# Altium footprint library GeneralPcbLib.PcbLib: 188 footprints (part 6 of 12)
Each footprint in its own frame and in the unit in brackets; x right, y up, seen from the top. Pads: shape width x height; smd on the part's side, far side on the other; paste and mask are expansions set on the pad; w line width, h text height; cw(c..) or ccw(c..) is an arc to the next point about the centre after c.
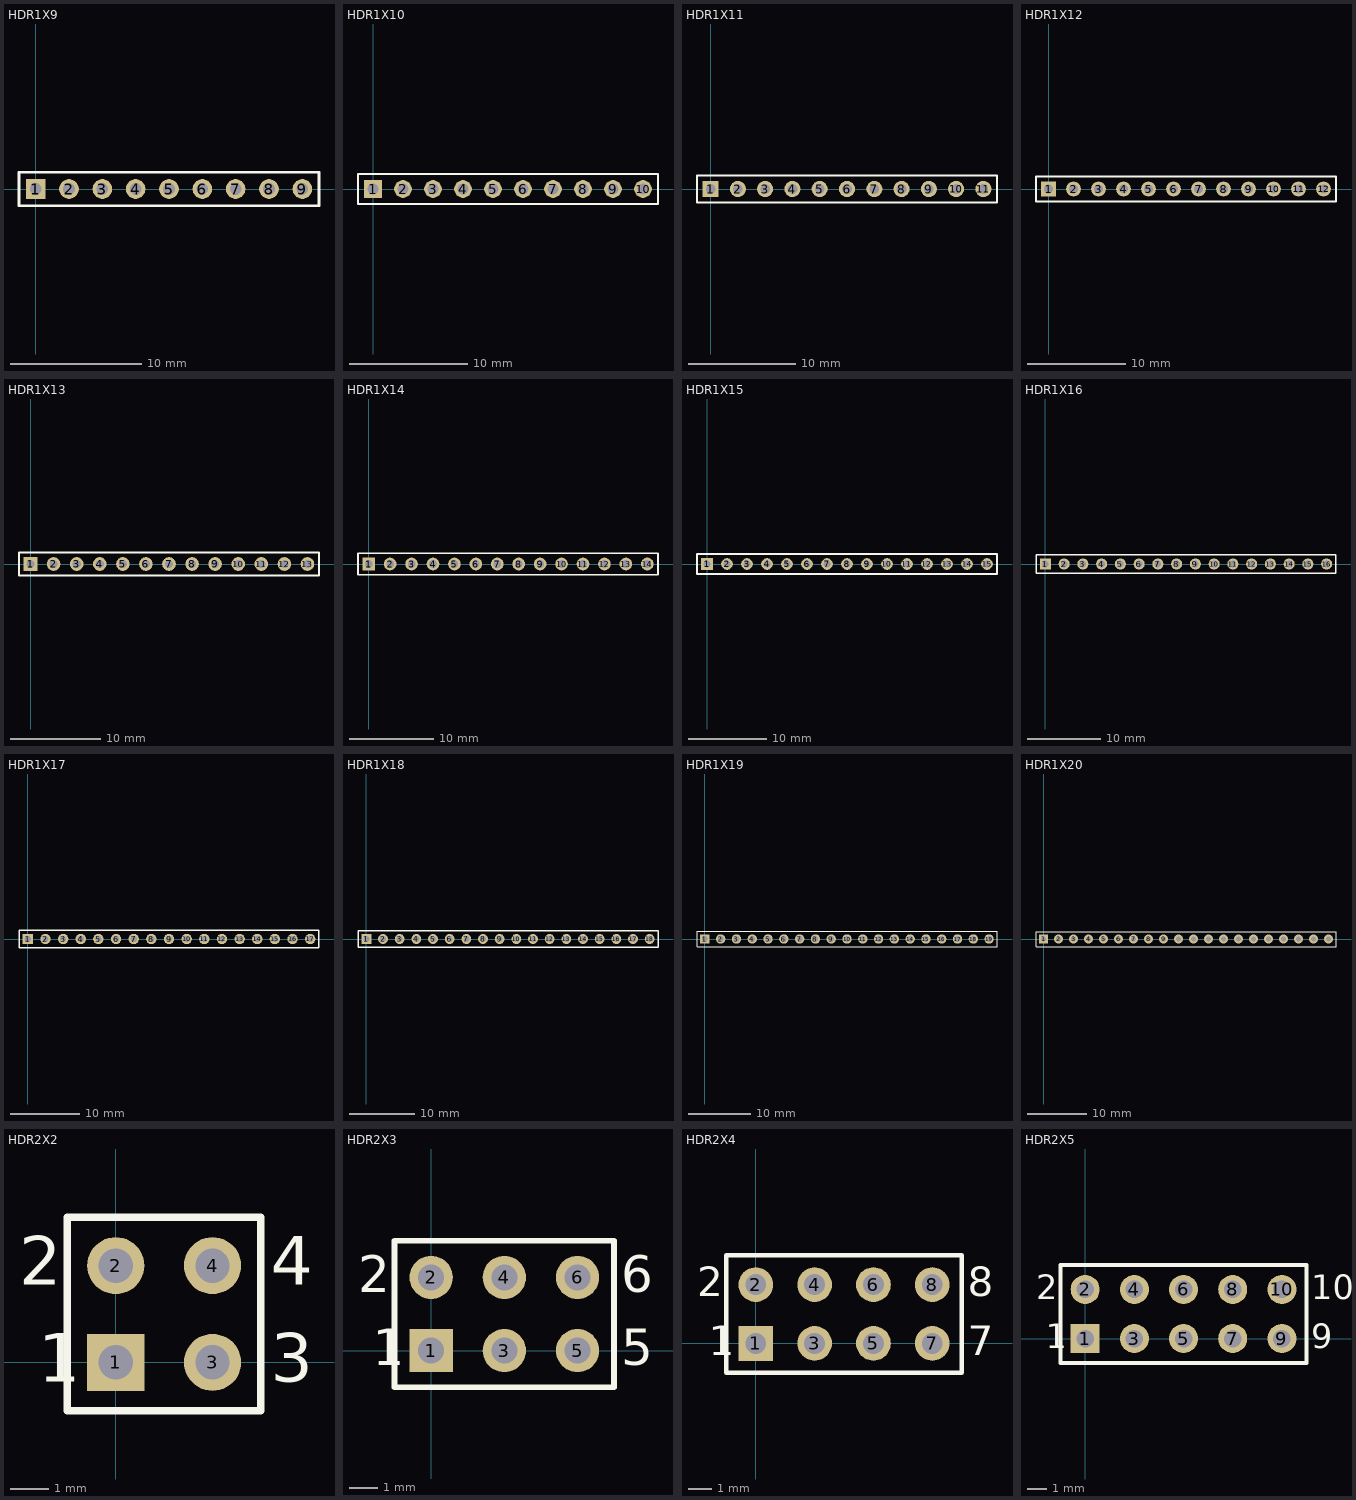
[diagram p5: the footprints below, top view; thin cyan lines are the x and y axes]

## HDR1X9 [mm] "Connector; Header; 9 Position"
pads (9):
  rect 1.5x1.5 hole 0.9: 1(0,0)
  round 1.5 hole 0.9: 2(2.54,0) 3(5.08,0) 4(7.62,0) 5(10.16,0) 6(12.7,0) 7(15.24,0) 8(17.78,0) 9(20.32,0)
Top Overlay:
  lines w0.2: -1.27,-1.27 21.59,-1.27 21.59,1.27 -1.27,1.27 -1.27,-1.27
3D body: height 7.58, standoff -2.94, extent 11.43,-1.27 13.97,1.27
3D body: height 7.58, standoff -2.94, extent 13.97,-1.27 16.51,1.27
3D body: height 7.58, standoff -2.94, extent 16.51,-1.27 19.05,1.27
3D body: height 7.58, standoff -2.94, extent 19.05,-1.27 21.59,1.27
3D body: height 7.58, standoff -2.94, extent 8.89,-1.27 11.43,1.27
3D body: height 7.58, standoff -2.94, extent 6.35,-1.27 8.89,1.27
3D body: height 7.58, standoff -2.94, extent 3.81,-1.27 6.35,1.27
3D body: height 7.58, standoff -2.94, extent 1.27,-1.27 3.81,1.27
3D body: height 7.58, standoff -2.94, extent -1.27,-1.27 1.27,1.27

## HDR1X10 [mm] "Connector; Header; 10 Position"
pads (10):
  rect 1.5x1.5 hole 0.9: 1(0,0)
  round 1.5 hole 0.9: 2(2.54,0) 3(5.08,0) 4(7.62,0) 5(10.16,0) 6(12.7,0) 7(15.24,0) 8(17.78,0) 9(20.32,0) 10(22.86,0)
Top Overlay:
  lines w0.2: -1.27,-1.27 24.13,-1.27 24.13,1.27 0.635,1.27 -1.27,1.27 -1.27,-1.27
3D body: height 7.58, standoff -2.94, extent 21.59,-1.27 24.13,1.27
3D body: height 7.58, standoff -2.94, extent 19.05,-1.27 21.59,1.27
3D body: height 7.58, standoff -2.94, extent 13.97,-1.27 16.51,1.27
3D body: height 7.58, standoff -2.94, extent 16.51,-1.27 19.05,1.27
3D body: height 7.58, standoff -2.94, extent 8.89,-1.27 11.43,1.27
3D body: height 7.58, standoff -2.94, extent 11.43,-1.27 13.97,1.27
3D body: height 7.58, standoff -2.94, extent 3.81,-1.27 6.35,1.27
3D body: height 7.58, standoff -2.94, extent 6.35,-1.27 8.89,1.27
3D body: height 7.58, standoff -2.94, extent 1.27,-1.27 3.81,1.27
3D body: height 7.58, standoff -2.94, extent -1.27,-1.27 1.27,1.27

## HDR1X11 [mm] "Connector; Header; 11 Position"
pads (11):
  rect 1.5x1.5 hole 0.9: 1(0,0)
  round 1.5 hole 0.9: 2(2.54,0) 3(5.08,0) 4(7.62,0) 5(10.16,0) 6(12.7,0) 7(15.24,0) 8(17.78,0) 9(20.32,0) 10(22.86,0) 11(25.4,0)
Top Overlay:
  lines w0.2: -1.27,-1.27 26.67,-1.27 26.67,1.27 0.635,1.27 -1.27,1.27 -1.27,-1.27
3D body: height 7.58, standoff -2.94, extent 24.13,-1.27 26.67,1.27
3D body: height 7.58, standoff -2.94, extent 21.59,-1.27 24.13,1.27
3D body: height 7.58, standoff -2.94, extent 19.05,-1.27 21.59,1.27
3D body: height 7.58, standoff -2.94, extent 16.51,-1.27 19.05,1.27
3D body: height 7.58, standoff -2.94, extent 13.97,-1.27 16.51,1.27
3D body: height 7.58, standoff -2.94, extent 11.43,-1.27 13.97,1.27
3D body: height 7.58, standoff -2.94, extent 8.89,-1.27 11.43,1.27
3D body: height 7.58, standoff -2.94, extent 6.35,-1.27 8.89,1.27
3D body: height 7.58, standoff -2.94, extent 3.81,-1.27 6.35,1.27
3D body: height 7.58, standoff -2.94, extent 1.27,-1.27 3.81,1.27
3D body: height 7.58, standoff -2.94, extent -1.27,-1.27 1.27,1.27

## HDR1X12 [mm] "Connector; Header; 12 Position"
pads (12):
  rect 1.5x1.5 hole 0.9: 1(0,0)
  round 1.5 hole 0.9: 2(2.54,0) 3(5.08,0) 4(7.62,0) 5(10.16,0) 6(12.7,0) 7(15.24,0) 8(17.78,0) 9(20.32,0) 10(22.86,0) 11(25.4,0) 12(27.94,0)
Top Overlay:
  lines w0.2: -1.27,-1.27 -1.27,1.27 0.635,1.27 29.21,1.27 29.21,-1.27 -1.27,-1.27
3D body: height 7.58, standoff -2.94, extent 26.67,-1.27 29.21,1.27
3D body: height 7.58, standoff -2.94, extent 24.13,-1.27 26.67,1.27
3D body: height 7.58, standoff -2.94, extent 21.59,-1.27 24.13,1.27
3D body: height 7.58, standoff -2.94, extent 19.05,-1.27 21.59,1.27
3D body: height 7.58, standoff -2.94, extent 16.51,-1.27 19.05,1.27
3D body: height 7.58, standoff -2.94, extent 13.97,-1.27 16.51,1.27
3D body: height 7.58, standoff -2.94, extent 11.43,-1.27 13.97,1.27
3D body: height 7.58, standoff -2.94, extent 8.89,-1.27 11.43,1.27
3D body: height 7.58, standoff -2.94, extent 6.35,-1.27 8.89,1.27
3D body: height 7.58, standoff -2.94, extent 3.81,-1.27 6.35,1.27
3D body: height 7.58, standoff -2.94, extent 1.27,-1.27 3.81,1.27
3D body: height 7.58, standoff -2.94, extent -1.27,-1.27 1.27,1.27

## HDR1X13 [mm] "Connector; Header; 13 Position"
pads (13):
  rect 1.5x1.5 hole 0.9: 1(0,0)
  round 1.5 hole 0.9: 2(2.54,0) 3(5.08,0) 4(7.62,0) 5(10.16,0) 6(12.7,0) 7(15.24,0) 8(17.78,0) 9(20.32,0) 10(22.86,0) 11(25.4,0) 12(27.94,0) 13(30.48,0)
Top Overlay:
  lines w0.2: -1.27,-1.27 -1.27,1.27 0.635,1.27 31.75,1.27 31.75,-1.27 -1.27,-1.27
3D body: height 7.58, standoff -2.94, extent 29.21,-1.27 31.75,1.27
3D body: height 7.58, standoff -2.94, extent 26.67,-1.27 29.21,1.27
3D body: height 7.58, standoff -2.94, extent 24.13,-1.27 26.67,1.27
3D body: height 7.58, standoff -2.94, extent 21.59,-1.27 24.13,1.27
3D body: height 7.58, standoff -2.94, extent 19.05,-1.27 21.59,1.27
3D body: height 7.58, standoff -2.94, extent 16.51,-1.27 19.05,1.27
3D body: height 7.58, standoff -2.94, extent 13.97,-1.27 16.51,1.27
3D body: height 7.58, standoff -2.94, extent 11.43,-1.27 13.97,1.27
3D body: height 7.58, standoff -2.94, extent 8.89,-1.27 11.43,1.27
3D body: height 7.58, standoff -2.94, extent 6.35,-1.27 8.89,1.27
3D body: height 7.58, standoff -2.94, extent 3.81,-1.27 6.35,1.27
3D body: height 7.58, standoff -2.94, extent 1.27,-1.27 3.81,1.27
3D body: height 7.58, standoff -2.94, extent -1.27,-1.27 1.27,1.27

## HDR1X14 [mm] "Connector; Header; 14 Position"
pads (14):
  rect 1.5x1.5 hole 0.9: 1(0,0)
  round 1.5 hole 0.9: 2(2.54,0) 3(5.08,0) 4(7.62,0) 5(10.16,0) 6(12.7,0) 7(15.24,0) 8(17.78,0) 9(20.32,0) 10(22.86,0) 11(25.4,0) 12(27.94,0) 13(30.48,0) 14(33.02,0)
Top Overlay:
  lines w0.2: -1.27,-1.27 34.29,-1.27 34.29,1.27 0.635,1.27 -1.27,1.27 -1.27,-1.27
3D body: height 7.58, standoff -2.94, extent 29.21,-1.27 31.75,1.27
3D body: height 7.58, standoff -2.94, extent 31.75,-1.27 34.29,1.27
3D body: height 7.58, standoff -2.94, extent 19.05,-1.27 21.59,1.27
3D body: height 7.58, standoff -2.94, extent 21.59,-1.27 24.13,1.27
3D body: height 7.58, standoff -2.94, extent 24.13,-1.27 26.67,1.27
3D body: height 7.58, standoff -2.94, extent 26.67,-1.27 29.21,1.27
3D body: height 7.58, standoff -2.94, extent 8.89,-1.27 11.43,1.27
3D body: height 7.58, standoff -2.94, extent 11.43,-1.27 13.97,1.27
3D body: height 7.58, standoff -2.94, extent 13.97,-1.27 16.51,1.27
3D body: height 7.58, standoff -2.94, extent 16.51,-1.27 19.05,1.27
3D body: height 7.58, standoff -2.94, extent 6.35,-1.27 8.89,1.27
3D body: height 7.58, standoff -2.94, extent 3.81,-1.27 6.35,1.27
3D body: height 7.58, standoff -2.94, extent 1.27,-1.27 3.81,1.27
3D body: height 7.58, standoff -2.94, extent -1.27,-1.27 1.27,1.27

## HDR1X15 [mm] "Connector; Header; 15 Position"
pads (15):
  rect 1.5x1.5 hole 0.9: 1(0,0)
  round 1.5 hole 0.9: 2(2.54,0) 3(5.08,0) 4(7.62,0) 5(10.16,0) 6(12.7,0) 7(15.24,0) 8(17.78,0) 9(20.32,0) 10(22.86,0) 11(25.4,0) 12(27.94,0) 13(30.48,0) 14(33.02,0) 15(35.56,0)
Top Overlay:
  lines w0.2: -1.27,-1.27 -1.27,1.27 0.635,1.27 36.83,1.27 36.83,-1.27 -1.27,-1.27
3D body: height 7.58, standoff -2.94, extent 29.21,-1.27 31.75,1.27
3D body: height 7.58, standoff -2.94, extent 31.75,-1.27 34.29,1.27
3D body: height 7.58, standoff -2.94, extent 34.29,-1.27 36.83,1.27
3D body: height 7.58, standoff -2.94, extent 19.05,-1.27 21.59,1.27
3D body: height 7.58, standoff -2.94, extent 21.59,-1.27 24.13,1.27
3D body: height 7.58, standoff -2.94, extent 24.13,-1.27 26.67,1.27
3D body: height 7.58, standoff -2.94, extent 26.67,-1.27 29.21,1.27
3D body: height 7.58, standoff -2.94, extent 8.89,-1.27 11.43,1.27
3D body: height 7.58, standoff -2.94, extent 11.43,-1.27 13.97,1.27
3D body: height 7.58, standoff -2.94, extent 13.97,-1.27 16.51,1.27
3D body: height 7.58, standoff -2.94, extent 16.51,-1.27 19.05,1.27
3D body: height 7.58, standoff -2.94, extent -1.27,-1.27 1.27,1.27
3D body: height 7.58, standoff -2.94, extent 1.27,-1.27 3.81,1.27
3D body: height 7.58, standoff -2.94, extent 3.81,-1.27 6.35,1.27
3D body: height 7.58, standoff -2.94, extent 6.35,-1.27 8.89,1.27

## HDR1X16 [mm] "Connector; Header; 16 Position"
pads (16):
  rect 1.5x1.5 hole 0.9: 1(0,0)
  round 1.5 hole 0.9: 2(2.54,0) 3(5.08,0) 4(7.62,0) 5(10.16,0) 6(12.7,0) 7(15.24,0) 8(17.78,0) 9(20.32,0) 10(22.86,0) 11(25.4,0) 12(27.94,0) 13(30.48,0) 14(33.02,0) 15(35.56,0) 16(38.1,0)
Top Overlay:
  lines w0.2: -1.27,-1.27 -1.27,1.27 0.635,1.27 39.37,1.27 39.37,-1.27 -1.27,-1.27
3D body: height 7.58, standoff -2.94, extent 29.21,-1.27 31.75,1.27
3D body: height 7.58, standoff -2.94, extent 31.75,-1.27 34.29,1.27
3D body: height 7.58, standoff -2.94, extent 34.29,-1.27 36.83,1.27
3D body: height 7.58, standoff -2.94, extent 36.83,-1.27 39.37,1.27
3D body: height 7.58, standoff -2.94, extent 19.05,-1.27 21.59,1.27
3D body: height 7.58, standoff -2.94, extent 21.59,-1.27 24.13,1.27
3D body: height 7.58, standoff -2.94, extent 24.13,-1.27 26.67,1.27
3D body: height 7.58, standoff -2.94, extent 26.67,-1.27 29.21,1.27
3D body: height 7.58, standoff -2.94, extent 8.89,-1.27 11.43,1.27
3D body: height 7.58, standoff -2.94, extent 11.43,-1.27 13.97,1.27
3D body: height 7.58, standoff -2.94, extent 13.97,-1.27 16.51,1.27
3D body: height 7.58, standoff -2.94, extent 16.51,-1.27 19.05,1.27
3D body: height 7.58, standoff -2.94, extent -1.27,-1.27 1.27,1.27
3D body: height 7.58, standoff -2.94, extent 1.27,-1.27 3.81,1.27
3D body: height 7.58, standoff -2.94, extent 3.81,-1.27 6.35,1.27
3D body: height 7.58, standoff -2.94, extent 6.35,-1.27 8.89,1.27

## HDR1X17 [mm] "Connector; Header; 17 Position"
pads (17):
  rect 1.5x1.5 hole 0.9: 1(0,0)
  round 1.5 hole 0.9: 2(2.54,0) 3(5.08,0) 4(7.62,0) 5(10.16,0) 6(12.7,0) 7(15.24,0) 8(17.78,0) 9(20.32,0) 10(22.86,0) 11(25.4,0) 12(27.94,0) 13(30.48,0) 14(33.02,0) 15(35.56,0) 16(38.1,0) 17(40.64,0)
Top Overlay:
  lines w0.2: -1.27,-1.27 41.91,-1.27 41.91,1.27 0.635,1.27 -1.27,1.27 -1.27,-1.27
3D body: height 7.58, standoff -2.94, extent 39.37,-1.27 41.91,1.27
3D body: height 7.58, standoff -2.94, extent 29.21,-1.27 31.75,1.27
3D body: height 7.58, standoff -2.94, extent 31.75,-1.27 34.29,1.27
3D body: height 7.58, standoff -2.94, extent 34.29,-1.27 36.83,1.27
3D body: height 7.58, standoff -2.94, extent 36.83,-1.27 39.37,1.27
3D body: height 7.58, standoff -2.94, extent 19.05,-1.27 21.59,1.27
3D body: height 7.58, standoff -2.94, extent 21.59,-1.27 24.13,1.27
3D body: height 7.58, standoff -2.94, extent 24.13,-1.27 26.67,1.27
3D body: height 7.58, standoff -2.94, extent 26.67,-1.27 29.21,1.27
3D body: height 7.58, standoff -2.94, extent 8.89,-1.27 11.43,1.27
3D body: height 7.58, standoff -2.94, extent 11.43,-1.27 13.97,1.27
3D body: height 7.58, standoff -2.94, extent 13.97,-1.27 16.51,1.27
3D body: height 7.58, standoff -2.94, extent 16.51,-1.27 19.05,1.27
3D body: height 7.58, standoff -2.94, extent -1.27,-1.27 1.27,1.27
3D body: height 7.58, standoff -2.94, extent 1.27,-1.27 3.81,1.27
3D body: height 7.58, standoff -2.94, extent 3.81,-1.27 6.35,1.27
3D body: height 7.58, standoff -2.94, extent 6.35,-1.27 8.89,1.27

## HDR1X18 [mm] "Connector; Header; 18 Position"
pads (18):
  rect 1.5x1.5 hole 0.9: 1(0,0)
  round 1.5 hole 0.9: 2(2.54,0) 3(5.08,0) 4(7.62,0) 5(10.16,0) 6(12.7,0) 7(15.24,0) 8(17.78,0) 9(20.32,0) 10(22.86,0) 11(25.4,0) 12(27.94,0) 13(30.48,0) 14(33.02,0) 15(35.56,0) 16(38.1,0) 17(40.64,0) 18(43.18,0)
Top Overlay:
  lines w0.2: -1.27,-1.27 44.45,-1.27 44.45,1.27 0.635,1.27 -1.27,1.27 -1.27,-1.27
3D body: height 7.58, standoff -2.94, extent 39.37,-1.27 41.91,1.27
3D body: height 7.58, standoff -2.94, extent 41.91,-1.27 44.45,1.27
3D body: height 7.58, standoff -2.94, extent 29.21,-1.27 31.75,1.27
3D body: height 7.58, standoff -2.94, extent 31.75,-1.27 34.29,1.27
3D body: height 7.58, standoff -2.94, extent 34.29,-1.27 36.83,1.27
3D body: height 7.58, standoff -2.94, extent 36.83,-1.27 39.37,1.27
3D body: height 7.58, standoff -2.94, extent 19.05,-1.27 21.59,1.27
3D body: height 7.58, standoff -2.94, extent 21.59,-1.27 24.13,1.27
3D body: height 7.58, standoff -2.94, extent 24.13,-1.27 26.67,1.27
3D body: height 7.58, standoff -2.94, extent 26.67,-1.27 29.21,1.27
3D body: height 7.58, standoff -2.94, extent 8.89,-1.27 11.43,1.27
3D body: height 7.58, standoff -2.94, extent 11.43,-1.27 13.97,1.27
3D body: height 7.58, standoff -2.94, extent 13.97,-1.27 16.51,1.27
3D body: height 7.58, standoff -2.94, extent 16.51,-1.27 19.05,1.27
3D body: height 7.58, standoff -2.94, extent -1.27,-1.27 1.27,1.27
3D body: height 7.58, standoff -2.94, extent 1.27,-1.27 3.81,1.27
3D body: height 7.58, standoff -2.94, extent 3.81,-1.27 6.35,1.27
3D body: height 7.58, standoff -2.94, extent 6.35,-1.27 8.89,1.27

## HDR1X19 [mm] "Connector; Header; 19 Position"
pads (19):
  rect 1.5x1.5 hole 0.9: 1(0,0)
  round 1.5 hole 0.9: 2(2.54,0) 3(5.08,0) 4(7.62,0) 5(10.16,0) 6(12.7,0) 7(15.24,0) 8(17.78,0) 9(20.32,0) 10(22.86,0) 11(25.4,0) 12(27.94,0) 13(30.48,0) 14(33.02,0) 15(35.56,0) 16(38.1,0) 17(40.64,0) 18(43.18,0) 19(45.72,0)
Top Overlay:
  lines w0.2: 37.465,1.27 37.677,1.27 ; -1.27,-1.27 46.99,-1.27 46.99,1.27 0.635,1.27 -1.27,1.27 -1.27,-1.27
3D body: height 7.58, standoff -2.94, extent 39.37,-1.27 41.91,1.27
3D body: height 7.58, standoff -2.94, extent 41.91,-1.27 44.45,1.27
3D body: height 7.58, standoff -2.94, extent 44.45,-1.27 46.99,1.27
3D body: height 7.58, standoff -2.94, extent 29.21,-1.27 31.75,1.27
3D body: height 7.58, standoff -2.94, extent 31.75,-1.27 34.29,1.27
3D body: height 7.58, standoff -2.94, extent 34.29,-1.27 36.83,1.27
3D body: height 7.58, standoff -2.94, extent 36.83,-1.27 39.37,1.27
3D body: height 7.58, standoff -2.94, extent 19.05,-1.27 21.59,1.27
3D body: height 7.58, standoff -2.94, extent 21.59,-1.27 24.13,1.27
3D body: height 7.58, standoff -2.94, extent 24.13,-1.27 26.67,1.27
3D body: height 7.58, standoff -2.94, extent 26.67,-1.27 29.21,1.27
3D body: height 7.58, standoff -2.94, extent 8.89,-1.27 11.43,1.27
3D body: height 7.58, standoff -2.94, extent 11.43,-1.27 13.97,1.27
3D body: height 7.58, standoff -2.94, extent 13.97,-1.27 16.51,1.27
3D body: height 7.58, standoff -2.94, extent 16.51,-1.27 19.05,1.27
3D body: height 7.58, standoff -2.94, extent -1.27,-1.27 1.27,1.27
3D body: height 7.58, standoff -2.94, extent 1.27,-1.27 3.81,1.27
3D body: height 7.58, standoff -2.94, extent 3.81,-1.27 6.35,1.27
3D body: height 7.58, standoff -2.94, extent 6.35,-1.27 8.89,1.27

## HDR1X20 [mm] "Connector; Header; 20 Position"
pads (20):
  rect 1.5x1.5 hole 0.9: 1(0,0)
  round 1.5 hole 0.9: 2(2.54,0) 3(5.08,0) 4(7.62,0) 5(10.16,0) 6(12.7,0) 7(15.24,0) 8(17.78,0) 9(20.32,0) 10(22.86,0) 11(25.4,0) 12(27.94,0) 13(30.48,0) 14(33.02,0) 15(35.56,0) 16(38.1,0) 17(40.64,0) 18(43.18,0) 19(45.72,0) 20(48.26,0)
Top Overlay:
  lines w0.2: -1.27,-1.27 49.53,-1.27 49.53,1.27 0.635,1.27 -1.27,1.27 -1.27,-1.27
3D body: height 7.58, standoff -2.94, extent 6.35,-1.27 8.89,1.27
3D body: height 7.58, standoff -2.94, extent 3.81,-1.27 6.35,1.27
3D body: height 7.58, standoff -2.94, extent 1.27,-1.27 3.81,1.27
3D body: height 7.58, standoff -2.94, extent -1.27,-1.27 1.27,1.27
3D body: height 7.58, standoff -2.94, extent 16.51,-1.27 19.05,1.27
3D body: height 7.58, standoff -2.94, extent 13.97,-1.27 16.51,1.27
3D body: height 7.58, standoff -2.94, extent 11.43,-1.27 13.97,1.27
3D body: height 7.58, standoff -2.94, extent 8.89,-1.27 11.43,1.27
3D body: height 7.58, standoff -2.94, extent 26.67,-1.27 29.21,1.27
3D body: height 7.58, standoff -2.94, extent 24.13,-1.27 26.67,1.27
3D body: height 7.58, standoff -2.94, extent 21.59,-1.27 24.13,1.27
3D body: height 7.58, standoff -2.94, extent 19.05,-1.27 21.59,1.27
3D body: height 7.58, standoff -2.94, extent 36.83,-1.27 39.37,1.27
3D body: height 7.58, standoff -2.94, extent 34.29,-1.27 36.83,1.27
3D body: height 7.58, standoff -2.94, extent 31.75,-1.27 34.29,1.27
3D body: height 7.58, standoff -2.94, extent 29.21,-1.27 31.75,1.27
3D body: height 7.58, standoff -2.94, extent 46.99,-1.27 49.53,1.27
3D body: height 7.58, standoff -2.94, extent 44.45,-1.27 46.99,1.27
3D body: height 7.58, standoff -2.94, extent 41.91,-1.27 44.45,1.27
3D body: height 7.58, standoff -2.94, extent 39.37,-1.27 41.91,1.27

## HDR2X2 [mm] "Connector; Header; 2x2 Position"
pads (4):
  rect 1.5x1.5 hole 0.9: 1(0,0)
  round 1.5 hole 0.9: 2(0,2.54) 3(2.54,0) 4(2.54,2.54)
Top Overlay:
  lines w0.2: -1.27,-1.27 3.81,-1.27 3.81,3.81 -1.27,3.81 -1.27,-1.27
  text "3" at 4.064,-0.508 h1.27
  text "4" at 4.064,2.032 h1.27
  text "2" at -2.54,2.032 h1.27
  text "1" at -2.032,-0.508 h1.27
3D body: height 7.58, standoff -2.94, extent 1.27,1.27 3.81,3.81
3D body: height 7.58, standoff -2.94, extent -1.27,1.27 1.27,3.81
3D body: height 7.58, standoff -2.94, extent 1.27,-1.27 3.81,1.27
3D body: height 7.58, standoff -2.94, extent -1.27,-1.27 1.27,1.27

## HDR2X3 [mm] "Connector; Header; 3x2 Position"
pads (6):
  rect 1.5x1.5 hole 0.9: 1(0,0)
  round 1.5 hole 0.9: 2(0,2.54) 3(2.54,0) 4(2.54,2.54) 5(5.08,0) 6(5.08,2.54)
Top Overlay:
  lines w0.2: 1.482,-1.27 6.35,-1.27 ; 6.35,-1.27 6.35,3.81 -1.27,3.81 -1.27,-1.27 6.35,-1.27
  text "6" at 6.604,2.032 h1.27
  text "5" at 6.604,-0.508 h1.27
  text "2" at -2.54,2.032 h1.27
  text "1" at -2.032,-0.508 h1.27
3D body: height 7.58, standoff -2.94, extent 1.27,1.27 3.81,3.81
3D body: height 7.58, standoff -2.94, extent -1.27,1.27 1.27,3.81
3D body: height 7.58, standoff -2.94, extent 1.27,-1.27 3.81,1.27
3D body: height 7.58, standoff -2.94, extent -1.27,-1.27 1.27,1.27
3D body: height 7.58, standoff -2.94, extent 3.81,-1.27 6.35,1.27
3D body: height 7.58, standoff -2.94, extent 3.81,1.27 6.35,3.81

## HDR2X4 [mm] "Connector; Header; 4x2 Position"
pads (8):
  rect 1.5x1.5 hole 0.9: 1(0,0)
  round 1.5 hole 0.9: 2(0,2.54) 3(2.54,0) 4(2.54,2.54) 5(5.08,0) 6(5.08,2.54) 7(7.62,0) 8(7.62,2.54)
Top Overlay:
  lines w0.2: -1.27,-1.27 -1.27,3.81 8.89,3.81 8.89,-1.27 -1.27,-1.27
  text "8" at 9.144,2.032 h1.27
  text "7" at 9.144,-0.508 h1.27
  text "1" at -2.032,-0.508 h1.27
  text "2" at -2.54,2.032 h1.27
3D body: height 7.58, standoff -2.94, extent 6.35,1.27 8.89,3.81
3D body: height 7.58, standoff -2.94, extent 6.35,-1.27 8.89,1.27
3D body: height 7.58, standoff -2.94, extent 1.27,1.27 3.81,3.81
3D body: height 7.58, standoff -2.94, extent -1.27,1.27 1.27,3.81
3D body: height 7.58, standoff -2.94, extent 1.27,-1.27 3.81,1.27
3D body: height 7.58, standoff -2.94, extent -1.27,-1.27 1.27,1.27
3D body: height 7.58, standoff -2.94, extent 3.81,-1.27 6.35,1.27
3D body: height 7.58, standoff -2.94, extent 3.81,1.27 6.35,3.81

## HDR2X5 [mm] "Connector; Header; 5x2 Position"
pads (10):
  rect 1.5x1.5 hole 0.9: 1(0,0)
  round 1.5 hole 0.9: 2(0,2.54) 3(2.54,0) 4(2.54,2.54) 5(5.08,0) 6(5.08,2.54) 7(7.62,0) 8(7.62,2.54) 9(10.16,0) 10(10.16,2.54)
Top Overlay:
  lines w0.2: -1.27,-1.27 -1.27,3.81 11.43,3.81 11.43,-1.27 -1.27,-1.27
  text "2" at -2.54,2.032 h1.27
  text "1" at -2.032,-0.508 h1.27
  text "9" at 11.684,-0.508 h1.27
  text "10" at 11.684,2.032 h1.27
3D body: height 7.58, standoff -2.94, extent 8.89,1.27 11.43,3.81
3D body: height 7.58, standoff -2.94, extent 8.89,-1.27 11.43,1.27
3D body: height 7.58, standoff -2.94, extent 6.35,1.27 8.89,3.81
3D body: height 7.58, standoff -2.94, extent 6.35,-1.27 8.89,1.27
3D body: height 7.58, standoff -2.94, extent 3.81,1.27 6.35,3.81
3D body: height 7.58, standoff -2.94, extent 3.81,-1.27 6.35,1.27
3D body: height 7.58, standoff -2.94, extent 1.27,1.27 3.81,3.81
3D body: height 7.58, standoff -2.94, extent 1.27,-1.27 3.81,1.27
3D body: height 7.58, standoff -2.94, extent -1.27,1.27 1.27,3.81
3D body: height 7.58, standoff -2.94, extent -1.27,-1.27 1.27,1.27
